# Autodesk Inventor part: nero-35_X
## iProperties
Shininess: 20.0
Length Units: 11269
Angle Units: 11279
Time Units: 11290
Mass Units: 11283
Length Display Precision: 2
Angle Display Precision: 2
Part Number: nero-35_X
Material: Nichtrostender Stahl - 440C
Document SubType Name: Modellieren
Description: Ipc-25 /CXX/M18
Checked By: Alves
Created: 2005-08
Designer: Ohle
Manufacturer: Standard
Standards Organization: Custom
Density: 0.0
Volumn: 0.0
Area: 0.0
PropertySet Name: Model Information
Control State: 0
Master: False
Checked Out: False
BESTELLNUMMER: Ipc-25 /CXX/M18
ME: ST
Title: Ipc Sensoren
Author: Ohle
Comments: keine Bemerkung
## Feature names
1. Grundkörper pico+ [Revolution]
2. Pole [Extrusion]
3. Rundung Pole [Fillet]
4. Verdrehsicherung [Extrusion]
5. Bohrung Ausrichtung [Extrusion]
